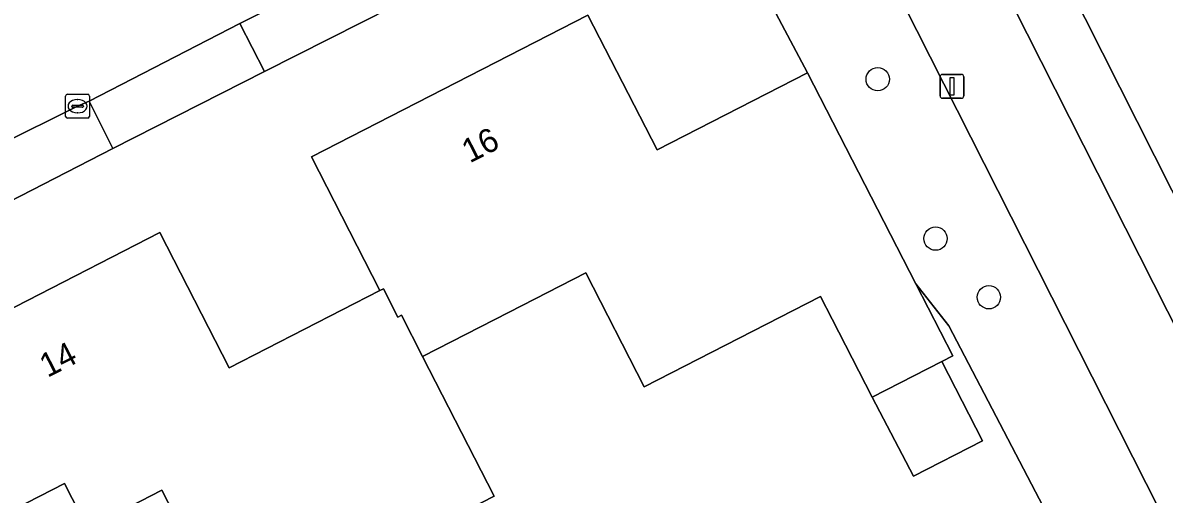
# Model space of a CAD drawing. Extents: x 162722 to 165104, y 384719 to 386284.
# Drawn here: x 163734.54 to 163782.39, y 384831.15 to 384850.92 of the extents above; entities that cross this region are included whole.
import ezdxf

# ---------------------------------------------------------------- set-up
doc = ezdxf.new("R2010")
doc.units = 0
for name, color, linetype in [('IMGEO_Berm_groen', 7, 'Continuous'), ('IMGEO_Boom', 7, 'Continuous'), ('IMGEO_Erf', 7, 'Continuous'), ('IMGEO_Fietspad_open', 7, 'Continuous'), ('IMGEO_Groenvoorziening', 7, 'Continuous'), ('IMGEO_Hek', 7, 'Continuous'), ('IMGEO_Kolk', 7, 'Continuous'), ('IMGEO_Lichtmast', 7, 'Continuous'), ('IMGEO_Pand', 7, 'Continuous'), ('IMGEO_Pand_nummerreeks', 7, 'Continuous'), ('IMGEO_Rijbaan_lokaal_open', 7, 'Continuous'), ('IMGEO_Voetpad_open', 7, 'Continuous')]:
    doc.layers.add(name, color=color, linetype=linetype)

msp = doc.modelspace()

# ---------------------------------------------------------------- linework, layer by layer
at = {"layer": 'IMGEO_Berm_groen'}
msp.add_lwpolyline([(163797.493, 384800.236), (163768.053, 384858.461), (163766.798, 384860.873), (163766.646, 384860.702), (163765.603, 384859.783), (163764.39, 384858.887), (163762.529, 384857.949), (163763.137, 384856.958), (163767.436, 384848.831), (163771.972, 384839.979), (163773.366, 384838.207), (163777.48, 384830.304), (163790.186, 384806.401), (163790.79, 384803.658)], dxfattribs=at)
at = {"layer": 'IMGEO_Boom'}
for centre in [(163770.378, 384848.557), (163772.804, 384841.869), (163775.04, 384839.409)]:
    msp.add_circle(centre, 0.489, dxfattribs=at)
at = {"layer": 'IMGEO_Erf'}
for points in [[(163778.51, 384877.58), (163776.526, 384877.488), (163775.31, 384877.306), (163774.677, 384876.823), (163770.692, 384867.742), (163771.093, 384866.945), (163784.89, 384839.576), (163787.19, 384840.813), (163787.523, 384840.14), (163789.755, 384835.805), (163804.848, 384844.548), (163822.396, 384853.228), (163841.154, 384861.667), (163840.837, 384862.308), (163876.056, 384880.802), (163873.969, 384885.011), (163858.338, 384916.535)], [(163729.169, 384836.424), (163740.286, 384842.121), (163743.191, 384836.453), (163749.509, 384839.691), (163746.634, 384845.301), (163758.231, 384851.244), (163761.125, 384845.596), (163767.436, 384848.831), (163763.137, 384856.958), (163762.529, 384857.949), (163759.521, 384856.413), (163744.666, 384848.886), (163738.311, 384845.645), (163727.158, 384839.91)], [(163759.065, 384821.045), (163777.48, 384830.304), (163773.366, 384838.207), (163771.972, 384839.979), (163773.522, 384836.953), (163773.061, 384836.717), (163774.77, 384833.383), (163771.879, 384831.902), (163770.146, 384835.223), (163768.472, 384838.488), (163767.984, 384839.44), (163760.593, 384835.653), (163758.142, 384840.435), (163754.931, 384838.79), (163751.296, 384836.928), (163754.302, 384831.061), (163750.675, 384829.203), (163750.103, 384830.319), (163742.791, 384826.571), (163740.362, 384831.311), (163737.243, 384829.712), (163736.28, 384831.592), (163732.597, 384829.704)]]:
    msp.add_lwpolyline(points, dxfattribs=at)
at = {"layer": 'IMGEO_Fietspad_open'}
for points in [[(163801.1, 384802.109), (163784.908, 384834.301), (163787.138, 384835.371), (163785.278, 384838.984), (163787.523, 384840.14), (163787.19, 384840.813), (163784.89, 384839.576), (163784.143, 384839.175), (163785.689, 384836.074), (163784.283, 384835.337), (163771.953, 384859.763), (163769.38, 384864.694), (163769.148, 384863.937)], [(163766.798, 384860.873), (163768.053, 384858.461), (163797.493, 384800.236)]]:
    msp.add_lwpolyline(points, dxfattribs=at)
at = {"layer": 'IMGEO_Groenvoorziening'}
msp.add_lwpolyline([(163784.89, 384839.576), (163771.093, 384866.945), (163770.692, 384867.742), (163769.977, 384866.113), (163769.38, 384864.694), (163771.953, 384859.763), (163784.283, 384835.337), (163785.689, 384836.074), (163784.143, 384839.175)], close=True, dxfattribs=at)
at = {"layer": 'IMGEO_Hek'}
msp.add_lwpolyline([(163777.48, 384830.304), (163773.366, 384838.207), (163771.972, 384839.979)], dxfattribs=at)
at = {"layer": 'IMGEO_Kolk'}
for p, q in [((163736.33, 384846.999), (163736.33, 384847.851)), ((163736.405, 384847.925), (163737.257, 384847.925)), ((163736.818, 384847.705), (163736.843, 384847.705)), ((163737.331, 384847.851), (163737.331, 384846.999)), ((163736.589, 384847.419), (163736.589, 384847.431)), ((163737.027, 384847.382), (163736.629, 384847.382)), ((163736.632, 384847.468), (163737.03, 384847.468)), ((163736.841, 384847.145), (163736.816, 384847.145)), ((163737.073, 384847.431), (163737.073, 384847.419)), ((163737.257, 384846.925), (163736.405, 384846.925))]:
    msp.add_line(p, q, dxfattribs=at)
for points in [[(163736.33, 384846.999), (163736.33, 384847.851)], [(163736.405, 384847.925), (163737.257, 384847.925)], [(163737.331, 384847.851), (163737.331, 384846.999)], [(163737.257, 384846.925), (163736.405, 384846.925)]]:
    msp.add_lwpolyline(points, dxfattribs=at)
for centre, radius, start, end in [((163736.407, 384847.849), 0.0765, 91.552, 178.448), ((163736.407, 384847.849), 0.0765, 91.552, 178.448), ((163737.255, 384847.849), 0.0765, 1.552, 88.448), ((163737.255, 384847.849), 0.0765, 1.552, 88.448), ((163736.629, 384847.428), 0.0403, 85.8775, 175.7526), ((163736.626, 384847.418), 0.0366, 178.938, 274.7102), ((163737.03, 384847.425), 0.043, 264.8664, 352.4533), ((163737.034, 384847.43), 0.0386, 1.7309, 96.639), ((163736.407, 384847.001), 0.0765, 181.552, 268.448), ((163736.407, 384847.001), 0.0765, 181.552, 268.448), ((163737.255, 384847.001), 0.0765, 271.552, 358.448), ((163737.255, 384847.001), 0.0765, 271.552, 358.448)]:
    msp.add_arc(centre, radius, start, end, dxfattribs=at)
for centre, major_axis, ratio, start_param, end_param in [((163736.817, 384847.425), (-0.387, 0.002), 0.722429, 4.712389, 7.853982), ((163736.842, 384847.425), (-0.39, 0.002), 0.717154, 1.570796, 4.712389)]:
    msp.add_ellipse(centre, major_axis=major_axis, ratio=ratio, start_param=start_param, end_param=end_param, dxfattribs=at)
at = {"layer": 'IMGEO_Lichtmast'}
for p, q in [((163772.994, 384847.86), (163772.994, 384848.66)), ((163772.994, 384848.66), (163772.994, 384847.86)), ((163773.094, 384848.76), (163773.884, 384848.76)), ((163773.884, 384848.76), (163773.094, 384848.76)), ((163773.984, 384848.66), (163773.984, 384847.86)), ((163773.984, 384847.86), (163773.984, 384848.66)), ((163773.884, 384847.76), (163773.094, 384847.76)), ((163773.094, 384847.76), (163773.884, 384847.76))]:
    msp.add_line(p, q, dxfattribs=at)
msp.add_lwpolyline([(163773.414, 384848.635), (163773.564, 384848.635), (163773.564, 384847.885), (163773.414, 384847.885), (163773.414, 384848.635)], dxfattribs=at)
for centre, start, end in [((163773.094, 384848.66), 90, 180), ((163773.094, 384848.66), 90, 180), ((163773.884, 384848.66), 0, 90), ((163773.884, 384848.66), 360, 90), ((163773.094, 384847.86), 180, 270), ((163773.094, 384847.86), 180, 270), ((163773.884, 384847.86), 270, 0), ((163773.884, 384847.86), 270, 0)]:
    msp.add_arc(centre, 0.1, start, end, dxfattribs=at)
at = {"layer": 'IMGEO_Pand'}
for points in [[(163767.436, 384848.831), (163761.125, 384845.596), (163758.231, 384851.244), (163746.634, 384845.301), (163749.509, 384839.691), (163749.653, 384839.763), (163750.262, 384838.574), (163750.412, 384838.652), (163751.296, 384836.928), (163754.931, 384838.79), (163758.142, 384840.435), (163760.593, 384835.653), (163767.984, 384839.44), (163768.472, 384838.488), (163770.146, 384835.223), (163773.061, 384836.717), (163773.522, 384836.953), (163771.972, 384839.979)], [(163732.597, 384829.704), (163736.28, 384831.592), (163737.243, 384829.712), (163740.362, 384831.311), (163742.791, 384826.571), (163750.103, 384830.319), (163750.675, 384829.203), (163754.302, 384831.061), (163751.296, 384836.928), (163750.412, 384838.652), (163750.262, 384838.574), (163749.653, 384839.763), (163749.509, 384839.691), (163743.191, 384836.453), (163740.286, 384842.121), (163729.169, 384836.424)], [(163773.061, 384836.717), (163770.146, 384835.223), (163771.879, 384831.902), (163774.77, 384833.383)]]:
    msp.add_lwpolyline(points, close=True, dxfattribs=at)
at = {"layer": 'IMGEO_Rijbaan_lokaal_open'}
msp.add_lwpolyline([(163733.497, 384845.778), (163736.831, 384847.425), (163737.316, 384847.642), (163743.627, 384850.894), (163748.211, 384853.215), (163758.493, 384858.439)], dxfattribs=at)
at = {"layer": 'IMGEO_Voetpad_open'}
msp.add_lwpolyline([(163724.121, 384847.618), (163724.495, 384847.949), (163721.534, 384851.578), (163715.953, 384858.469), (163714.216, 384857.037), (163724.179, 384844.915), (163727.158, 384839.91), (163738.311, 384845.645), (163737.316, 384847.642), (163736.831, 384847.425), (163733.497, 384845.778), (163733.722, 384845.329)], dxfattribs=at)
for points in [[(163758.493, 384858.439), (163748.211, 384853.215), (163743.627, 384850.894), (163744.666, 384848.886), (163759.521, 384856.413)], [(163737.316, 384847.642), (163738.311, 384845.645), (163744.666, 384848.886), (163743.627, 384850.894)]]:
    msp.add_lwpolyline(points, close=True, dxfattribs=at)

# ---------------------------------------------------------------- texts
at = {"layer": 'IMGEO_Pand_nummerreeks'}
for s, rotation, p in [('16', 27.1353, (163753.274, 384845.019)), ('14', 27.1333, (163735.569, 384836.019))]:
    msp.add_text(s, height=1, rotation=rotation, dxfattribs=at).set_placement(p)

doc.saveas('drawing.dxf')
